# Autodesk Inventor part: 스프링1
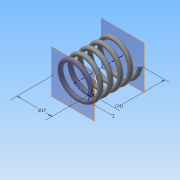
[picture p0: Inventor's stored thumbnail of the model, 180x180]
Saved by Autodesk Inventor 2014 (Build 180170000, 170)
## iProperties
Created: 2016-01
Part Number: 스프링1
Material: 강철, 탄소
Document SubType Name: Modeling
Designer: Administrator
Density: 7.87 g/cm^3
Appearance: 반연마
Mass: 6.47306 g
Surface Area: 16.7315 cm^2
Volume: 0.822499 cm^3
Author: Administrator
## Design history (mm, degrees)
sketch "스케치1"
  geometry: L1 (0, 0)-(8.5, 0); L2 (8.5, 0)-(8.5, 20.5); L3 (8.5, 20.5)-(0, 20.5); L4 (0, 20.5)-(0, 0); C1 r 1 at (8.5, 0)
  constraints: 8 end point, 2 parallel, 1 centre point, 1 coincident, 1 horizontal, 1 perpendicular
  dimensions: "d0" = 20.5 distance of L1.end L2.end (derived); "d1" = 17 diameter of L2 L4; "d2" = 2 diameter of C1
feature "코일1" pitch "d3" = 10; turns "d5" = 5; dims "d4" = 20.5 (= d0), "d6" = 0, angle "d7" = 90 deg, angle "d8" = 90 deg, "d9" = 0, "d10" = 0
node "작업 평면1"
sketch "스케치2"
  geometry: L1 (-7.5, 0)-(-9.5, 0) reference; L2 (-7.5, 0)-(-9.5, 0) reference; 1 further point
  constraints: 2 horizontal alignment
extrude "돌출1" cut sketch "스케치2" distance "d12" = 10; taper "d13" = 0 deg
node "작업 평면2"
sketch "스케치3"
  geometry: L1 (-9.5, 0)-(-7.5, 0) reference; 1 further point
  constraints: 1 horizontal alignment
extrude "돌출2" cut sketch "스케치3" distance "d15" = 10; taper "d16" = 0 deg
node "솔리드1"
node "절단 모서리 투영1"
node "절단 모서리 투영2"
node "절단 모서리 투영3"
other parameters: "d11" = 0, "d14" = 20.5 (= d0)
